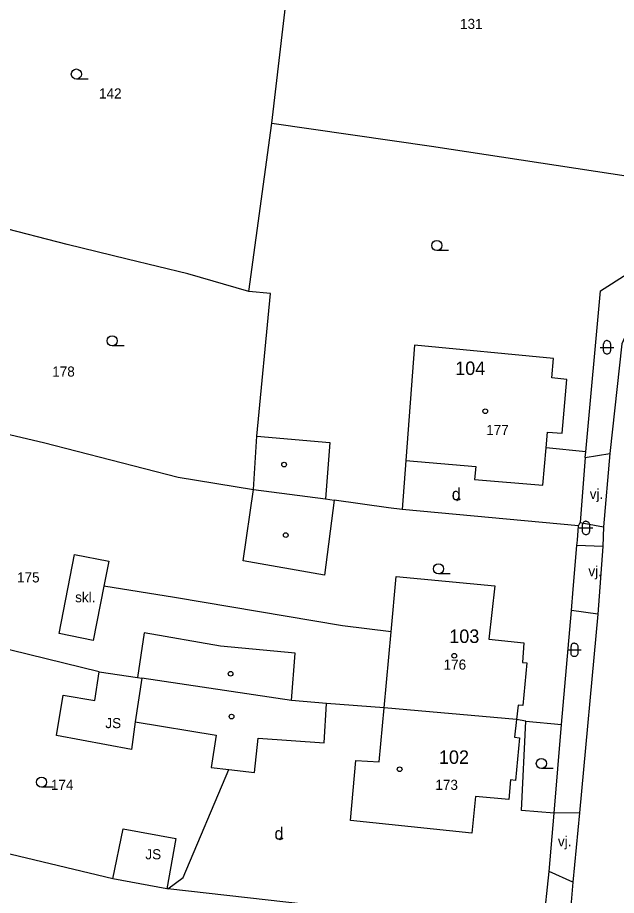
# Model space of a CAD drawing. Extents: x -836739 to -835945, y -1070775 to -1070126.
# Drawn here: x -836577.4 to -836533, y -1070514.1 to -1070449 of the extents above; entities that cross this region are included whole.
import ezdxf

# ---------------------------------------------------------------- set-up
doc = ezdxf.new("R2010")
doc.units = 0
for name, color, linetype in [('BodPole_mer', 7, 'Continuous'), ('Budovy_hranice', 7, 'Continuous'), ('Budovy_kody', 7, 'Continuous'), ('Doprava_hranice', 7, 'Continuous'), ('Doprava_kody', 7, 'Continuous'), ('OstPloch_kody', 7, 'Continuous'), ('RuianAdr_popis', 7, 'Continuous'), ('RuianPar_popis', 7, 'Continuous'), ('Stavby_hr_stav', 7, 'Continuous'), ('Stavby_kody', 7, 'Continuous'), ('Stavby_linie', 7, 'Continuous'), ('Zelen_linie', 7, 'Continuous')]:
    doc.layers.add(name, color=color, linetype=linetype)

msp = doc.modelspace()

# ---------------------------------------------------------------- linework, layer by layer
at = {"layer": 'BodPole_mer'}
for p, q in [((-836558.53, -1070456.83), (-836558.53, -1070456.83)), ((-836546.69, -1070458.52), (-836546.69, -1070458.52)), ((-836573.73, -1070465.81), (-836573.73, -1070465.81)), ((-836569.26, -1070466.91), (-836569.26, -1070466.91)), ((-836564.76, -1070467.99), (-836564.76, -1070467.99)), ((-836534.16, -1070469.25), (-836534.16, -1070469.25)), ((-836560.24, -1070469.31), (-836560.24, -1070469.31)), ((-836558.64, -1070469.45), (-836558.64, -1070469.45)), ((-836547.95, -1070473.29), (-836547.95, -1070473.29)), ((-836537.65, -1070474.28), (-836537.65, -1070474.28)), ((-836537.77, -1070475.71), (-836537.77, -1070475.71)), ((-836536.65, -1070475.84), (-836536.65, -1070475.84)), ((-836559.66, -1070480.04), (-836559.66, -1070480.04)), ((-836538.1, -1070479.75), (-836538.1, -1070479.75)), ((-836537.01, -1070479.82), (-836537.01, -1070479.82)), ((-836575.47, -1070480.52), (-836575.47, -1070480.52)), ((-836554.23, -1070480.51), (-836554.23, -1070480.51)), ((-836538.2, -1070480.91), (-836538.2, -1070480.91)), ((-836535.29, -1070481.63), (-836535.29, -1070481.63)), ((-836535.24, -1070481.2), (-836535.24, -1070481.2)), ((-836533.47, -1070481.32), (-836533.47, -1070481.32)), ((-836548.61, -1070481.84), (-836548.61, -1070481.84)), ((-836543.42, -1070482.28), (-836543.42, -1070482.28)), ((-836565.48, -1070483.09), (-836565.48, -1070483.09)), ((-836543.5, -1070483.26), (-836543.5, -1070483.26)), ((-836559.91, -1070484), (-836559.91, -1070484)), ((-836538.43, -1070483.68), (-836538.43, -1070483.68)), ((-836554.56, -1070484.7), (-836554.56, -1070484.7)), ((-836553.92, -1070484.79), (-836553.92, -1070484.79)), ((-836549.89, -1070485.36), (-836549.89, -1070485.36)), ((-836548.87, -1070485.47), (-836548.87, -1070485.47)), ((-836535.79, -1070486.7), (-836535.79, -1070486.7)), ((-836535.67, -1070486.44), (-836535.67, -1070486.44)), ((-836533.93, -1070486.76), (-836533.93, -1070486.76)), ((-836535.88, -1070487.76), (-836535.88, -1070487.76)), ((-836535.92, -1070488.16), (-836535.92, -1070488.16)), ((-836533.99, -1070488.23), (-836533.99, -1070488.23)), ((-836573.18, -1070488.82), (-836573.18, -1070488.82)), ((-836570.64, -1070489.32), (-836570.64, -1070489.32)), ((-836560.66, -1070489.28), (-836560.66, -1070489.28)), ((-836554.63, -1070490.36), (-836554.63, -1070490.36)), ((-836549.32, -1070490.45), (-836549.32, -1070490.45)), ((-836571, -1070491.16), (-836571, -1070491.16)), ((-836541.99, -1070491.13), (-836541.99, -1070491.13)), ((-836536.18, -1070491.38), (-836536.18, -1070491.38)), ((-836565.76, -1070492.01), (-836565.76, -1070492.01)), ((-836536.32, -1070492.98), (-836536.32, -1070492.98)), ((-836534.36, -1070493.24), (-836534.36, -1070493.24)), ((-836568.01, -1070494.63), (-836568.01, -1070494.63)), ((-836553.29, -1070494.12), (-836553.29, -1070494.12)), ((-836549.7, -1070494.55), (-836549.7, -1070494.55)), ((-836574.31, -1070494.69), (-836574.31, -1070494.69)), ((-836571.79, -1070495.19), (-836571.79, -1070495.19)), ((-836542.44, -1070495.09), (-836542.44, -1070495.09)), ((-836562.36, -1070495.62), (-836562.36, -1070495.62)), ((-836539.84, -1070495.37), (-836539.84, -1070495.37)), ((-836556.81, -1070496.13), (-836556.81, -1070496.13)), ((-836539.96, -1070496.83), (-836539.96, -1070496.83)), ((-836539.62, -1070496.86), (-836539.62, -1070496.86)), ((-836571.36, -1070497.51), (-836571.36, -1070497.51)), ((-836568.5, -1070497.94), (-836568.5, -1070497.94)), ((-836568.18, -1070497.98), (-836568.18, -1070497.98)), ((-836574.02, -1070499.26), (-836574.02, -1070499.26)), ((-836571.68, -1070499.66), (-836571.68, -1070499.66)), ((-836557.09, -1070499.64), (-836557.09, -1070499.64)), ((-836554.49, -1070499.87), (-836554.49, -1070499.87)), ((-836550.21, -1070500.19), (-836550.21, -1070500.19)), ((-836540.27, -1070500), (-836540.27, -1070500)), ((-836539.93, -1070500.03), (-836539.93, -1070500.03)), ((-836540.39, -1070501.06), (-836540.39, -1070501.06)), ((-836568.68, -1070501.24), (-836568.68, -1070501.24)), ((-836539.71, -1070501.19), (-836539.71, -1070501.19)), ((-836537.06, -1070501.42), (-836537.06, -1070501.42)), ((-836574.52, -1070502.25), (-836574.52, -1070502.25)), ((-836562.67, -1070502.22), (-836562.67, -1070502.22)), ((-836559.56, -1070502.45), (-836559.56, -1070502.45)), ((-836540.53, -1070502.37), (-836540.53, -1070502.37)), ((-836540.18, -1070502.42), (-836540.18, -1070502.42)), ((-836554.66, -1070502.78), (-836554.66, -1070502.78)), ((-836568.96, -1070503.28), (-836568.96, -1070503.28)), ((-836552.31, -1070504.09), (-836552.31, -1070504.09)), ((-836550.58, -1070504.19), (-836550.58, -1070504.19)), ((-836563.03, -1070504.61), (-836563.03, -1070504.61)), ((-836561.74, -1070504.76), (-836561.74, -1070504.76)), ((-836559.83, -1070504.98), (-836559.83, -1070504.98)), ((-836540.83, -1070505.53), (-836540.83, -1070505.53)), ((-836540.46, -1070505.58), (-836540.46, -1070505.58)), ((-836543.43, -1070506.77), (-836543.43, -1070506.77)), ((-836540.95, -1070507), (-836540.95, -1070507)), ((-836540.01, -1070507.8), (-836540.01, -1070507.8)), ((-836537.59, -1070508), (-836537.59, -1070508)), ((-836535.73, -1070507.97), (-836535.73, -1070507.97)), ((-836552.71, -1070508.55), (-836552.71, -1070508.55)), ((-836569.58, -1070509.17), (-836569.58, -1070509.17)), ((-836543.71, -1070509.48), (-836543.71, -1070509.48)), ((-836565.67, -1070509.88), (-836565.67, -1070509.88)), ((-836570.33, -1070512.89), (-836570.33, -1070512.89)), ((-836565.13, -1070512.77), (-836565.13, -1070512.77)), ((-836537.96, -1070512.33), (-836537.96, -1070512.33)), ((-836536.22, -1070513.12), (-836536.22, -1070513.12)), ((-836566.34, -1070513.61), (-836566.34, -1070513.61)), ((-836566.25, -1070513.62), (-836566.25, -1070513.62))]:
    msp.add_line(p, q, dxfattribs=at)
at = {"layer": 'Budovy_hranice'}
for points in [[(-836538.43, -1070483.68), (-836538.2, -1070480.91), (-836538.1, -1070479.75), (-836537.01, -1070479.82), (-836536.65, -1070475.84), (-836537.77, -1070475.71), (-836537.65, -1070474.28), (-836547.95, -1070473.29), (-836548.61, -1070481.84), (-836543.42, -1070482.28), (-836543.5, -1070483.26), (-836538.43, -1070483.68)], [(-836559.91, -1070484), (-836559.66, -1070480.04), (-836554.23, -1070480.51), (-836554.56, -1070484.7)], [(-836554.63, -1070490.36), (-836560.66, -1070489.28), (-836559.91, -1070484), (-836554.56, -1070484.7), (-836553.92, -1070484.79), (-836554.63, -1070490.36)], [(-836539.84, -1070495.37), (-836539.96, -1070496.83), (-836539.62, -1070496.86), (-836539.93, -1070500.03), (-836540.27, -1070500), (-836540.39, -1070501.06), (-836550.21, -1070500.19), (-836549.7, -1070494.55), (-836549.32, -1070490.45), (-836541.99, -1070491.13), (-836542.44, -1070495.09), (-836539.84, -1070495.37)], [(-836557.09, -1070499.64), (-836556.81, -1070496.13), (-836562.36, -1070495.62), (-836568.01, -1070494.63), (-836568.5, -1070497.94), (-836568.18, -1070497.98)], [(-836557.09, -1070499.64), (-836568.18, -1070497.98), (-836568.68, -1070501.24), (-836562.67, -1070502.22), (-836563.03, -1070504.61), (-836561.74, -1070504.76), (-836559.83, -1070504.98), (-836559.56, -1070502.45), (-836554.66, -1070502.78), (-836554.49, -1070499.87), (-836557.09, -1070499.64)], [(-836543.43, -1070506.77), (-836543.71, -1070509.48), (-836552.71, -1070508.55), (-836552.31, -1070504.09), (-836550.58, -1070504.19), (-836550.21, -1070500.19)], [(-836540.39, -1070501.06), (-836540.53, -1070502.37), (-836540.18, -1070502.42), (-836540.46, -1070505.58), (-836540.83, -1070505.53), (-836540.95, -1070507), (-836543.43, -1070506.77)]]:
    msp.add_lwpolyline(points, dxfattribs=at)
at = {"layer": 'Budovy_kody'}
for centre in [(-836542.71, -1070478.19), (-836557.63, -1070482.15), (-836557.51, -1070487.38), (-836545.01, -1070496.33), (-836561.6, -1070497.66), (-836561.53, -1070500.84), (-836549.06, -1070504.75)]:
    msp.add_circle(centre, 0.175, dxfattribs=at)
at = {"layer": 'Doprava_hranice'}
for p, q in [((-836535.29, -1070481.63), (-836533.47, -1070481.32)), ((-836535.67, -1070486.44), (-836533.93, -1070486.76)), ((-836533.99, -1070488.23), (-836535.92, -1070488.16)), ((-836534.36, -1070493.24), (-836536.32, -1070492.98)), ((-836535.73, -1070507.97), (-836537.59, -1070508)), ((-836536.22, -1070513.12), (-836537.96, -1070512.33))]:
    msp.add_line(p, q, dxfattribs=at)
msp.add_lwpolyline([(-836531.1, -1070469.82), (-836532.59, -1070473.19), (-836533.47, -1070481.32), (-836533.93, -1070486.76), (-836533.99, -1070488.23), (-836534.36, -1070493.24), (-836535.73, -1070507.97), (-836536.22, -1070513.12), (-836536.82, -1070520.24), (-836537.38, -1070525.89), (-836537.98, -1070532.4), (-836538.73, -1070540.19), (-836539.5, -1070548.26)], dxfattribs=at)
at = {"layer": 'OstPloch_kody'}
for p, q in [((-836572.165, -1070453.55), (-836573.04, -1070453.55)), ((-836545.425, -1070466.27), (-836546.3, -1070466.27)), ((-836569.505, -1070473.34), (-836570.38, -1070473.34)), ((-836534.18, -1070473.45), (-836533.18, -1070473.45)), ((-836533.93, -1070473.7), (-836533.93, -1070473.2)), ((-836533.43, -1070473.2), (-836533.43, -1070473.7)), ((-836535.49, -1070487.1), (-836535.49, -1070486.6)), ((-836534.99, -1070486.6), (-836534.99, -1070487.1)), ((-836535.74, -1070486.85), (-836534.74, -1070486.85)), ((-836545.305, -1070490.26), (-836546.18, -1070490.26)), ((-836536.6, -1070495.89), (-836535.6, -1070495.89)), ((-836536.35, -1070496.14), (-836536.35, -1070495.64)), ((-836535.85, -1070495.64), (-836535.85, -1070496.14)), ((-836537.675, -1070504.7), (-836538.55, -1070504.7)), ((-836574.745, -1070506.08), (-836575.62, -1070506.08))]:
    msp.add_line(p, q, dxfattribs=at)
for points in [[(-836533.68, -1070472.95), (-836533.725, -1070472.954), (-836533.772, -1070472.968), (-836533.817, -1070472.991), (-836533.857, -1070473.023), (-836533.889, -1070473.063), (-836533.912, -1070473.108), (-836533.926, -1070473.155), (-836533.93, -1070473.2)], [(-836533.68, -1070472.95), (-836533.635, -1070472.954), (-836533.588, -1070472.968), (-836533.543, -1070472.991), (-836533.503, -1070473.023), (-836533.471, -1070473.063), (-836533.448, -1070473.108), (-836533.434, -1070473.155), (-836533.43, -1070473.2)], [(-836533.68, -1070473.95), (-836533.725, -1070473.946), (-836533.772, -1070473.932), (-836533.817, -1070473.909), (-836533.857, -1070473.877), (-836533.889, -1070473.837), (-836533.912, -1070473.792), (-836533.926, -1070473.745), (-836533.93, -1070473.7)], [(-836533.43, -1070473.7), (-836533.434, -1070473.745), (-836533.448, -1070473.792), (-836533.471, -1070473.837), (-836533.503, -1070473.877), (-836533.543, -1070473.909), (-836533.588, -1070473.932), (-836533.635, -1070473.946), (-836533.68, -1070473.95)], [(-836544.819, -1070484.79), (-836544.819, -1070484.795), (-836544.818, -1070484.801), (-836544.81, -1070484.805), (-836544.793, -1070484.803), (-836544.763, -1070484.794), (-836544.715, -1070484.773), (-836544.647, -1070484.737), (-836544.554, -1070484.684)], [(-836535.24, -1070486.35), (-836535.285, -1070486.354), (-836535.332, -1070486.368), (-836535.377, -1070486.391), (-836535.417, -1070486.423), (-836535.449, -1070486.463), (-836535.472, -1070486.508), (-836535.486, -1070486.555), (-836535.49, -1070486.6)], [(-836535.24, -1070486.35), (-836535.195, -1070486.354), (-836535.148, -1070486.368), (-836535.103, -1070486.391), (-836535.063, -1070486.423), (-836535.031, -1070486.463), (-836535.008, -1070486.508), (-836534.994, -1070486.555), (-836534.99, -1070486.6)], [(-836535.24, -1070487.35), (-836535.285, -1070487.346), (-836535.332, -1070487.332), (-836535.377, -1070487.309), (-836535.417, -1070487.277), (-836535.449, -1070487.237), (-836535.472, -1070487.192), (-836535.486, -1070487.145), (-836535.49, -1070487.1)], [(-836534.99, -1070487.1), (-836534.994, -1070487.145), (-836535.008, -1070487.192), (-836535.031, -1070487.237), (-836535.063, -1070487.277), (-836535.103, -1070487.309), (-836535.148, -1070487.332), (-836535.195, -1070487.346), (-836535.24, -1070487.35)], [(-836536.1, -1070495.39), (-836536.145, -1070495.394), (-836536.192, -1070495.408), (-836536.237, -1070495.431), (-836536.277, -1070495.463), (-836536.309, -1070495.503), (-836536.332, -1070495.548), (-836536.346, -1070495.595), (-836536.35, -1070495.64)], [(-836536.1, -1070495.39), (-836536.055, -1070495.394), (-836536.008, -1070495.408), (-836535.963, -1070495.431), (-836535.923, -1070495.463), (-836535.891, -1070495.503), (-836535.868, -1070495.548), (-836535.854, -1070495.595), (-836535.85, -1070495.64)], [(-836536.1, -1070496.39), (-836536.145, -1070496.386), (-836536.192, -1070496.372), (-836536.237, -1070496.349), (-836536.277, -1070496.317), (-836536.309, -1070496.277), (-836536.332, -1070496.232), (-836536.346, -1070496.185), (-836536.35, -1070496.14)], [(-836535.85, -1070496.14), (-836535.854, -1070496.185), (-836535.868, -1070496.232), (-836535.891, -1070496.277), (-836535.923, -1070496.317), (-836535.963, -1070496.349), (-836536.008, -1070496.372), (-836536.055, -1070496.386), (-836536.1, -1070496.39)], [(-836557.969, -1070509.96), (-836557.969, -1070509.965), (-836557.968, -1070509.971), (-836557.96, -1070509.975), (-836557.943, -1070509.973), (-836557.913, -1070509.964), (-836557.865, -1070509.943), (-836557.797, -1070509.907), (-836557.704, -1070509.854)]]:
    msp.add_lwpolyline(points, dxfattribs=at)
for centre in [(-836573.04, -1070453.175), (-836546.3, -1070465.895), (-836570.38, -1070472.965), (-836546.18, -1070489.885), (-836538.55, -1070504.325), (-836575.62, -1070505.705)]:
    msp.add_ellipse(centre, major_axis=(0.375, 0), ratio=0.999999, dxfattribs=at)
at = {"layer": 'RuianAdr_popis'}
for p, q in [((-836544.94, -1070475.5), (-836544.94, -1070475.5)), ((-836545.38, -1070495.38), (-836545.38, -1070495.38)), ((-836546.15, -1070504.35), (-836546.15, -1070504.35))]:
    msp.add_line(p, q, dxfattribs=at)
at = {"layer": 'RuianPar_popis'}
for p, q in [((-836544.58, -1070449.83), (-836544.58, -1070449.83)), ((-836571.36, -1070454.99), (-836571.36, -1070454.99)), ((-836574.83, -1070475.62), (-836574.83, -1070475.62)), ((-836542.64, -1070479.95), (-836542.64, -1070479.95)), ((-836545.8, -1070497.36), (-836545.8, -1070497.36)), ((-836574.93, -1070506.28), (-836574.93, -1070506.28)), ((-836546.41, -1070506.28), (-836546.41, -1070506.28))]:
    msp.add_line(p, q, dxfattribs=at)
at = {"layer": 'Stavby_hr_stav'}
for points in [[(-836570.64, -1070489.32), (-836571, -1070491.16), (-836571.79, -1070495.19), (-836574.31, -1070494.69), (-836573.18, -1070488.82), (-836570.64, -1070489.32)], [(-836568.68, -1070501.24), (-836568.96, -1070503.28), (-836574.52, -1070502.25), (-836574.02, -1070499.26), (-836571.68, -1070499.66), (-836571.36, -1070497.51), (-836568.5, -1070497.94)], [(-836570.33, -1070512.89), (-836569.58, -1070509.17), (-836565.67, -1070509.88), (-836566.34, -1070513.61), (-836570.33, -1070512.89)]]:
    msp.add_lwpolyline(points, dxfattribs=at)
at = {"layer": 'Stavby_linie'}
for p, q in [((-836573.73, -1070465.81), (-836587.35, -1070462.31)), ((-836535.24, -1070481.2), (-836538.2, -1070480.91)), ((-836535.29, -1070481.63), (-836535.67, -1070486.44)), ((-836548.61, -1070481.84), (-836548.87, -1070485.47)), ((-836565.48, -1070483.09), (-836559.91, -1070484)), ((-836550.21, -1070500.19), (-836554.49, -1070499.87)), ((-836539.71, -1070501.19), (-836537.06, -1070501.42)), ((-836537.59, -1070508), (-836537.06, -1070501.42)), ((-836537.96, -1070512.33), (-836537.59, -1070508))]:
    msp.add_line(p, q, dxfattribs=at)
for points in [[(-836560.24, -1070469.31), (-836558.53, -1070456.83), (-836556.87, -1070442.42), (-836554.53, -1070432.32), (-836553.8, -1070429), (-836550.67, -1070422.72)], [(-836535.29, -1070481.63), (-836535.24, -1070481.2), (-836534.16, -1070469.25), (-836530.49, -1070466.92), (-836529.34, -1070461.16), (-836525.7, -1070445.11)], [(-836558.53, -1070456.83), (-836546.69, -1070458.52), (-836529.34, -1070461.16)], [(-836560.24, -1070469.31), (-836564.76, -1070467.99), (-836569.26, -1070466.91), (-836573.73, -1070465.81)], [(-836559.66, -1070480.04), (-836558.64, -1070469.45), (-836560.24, -1070469.31)], [(-836589.2, -1070477.29), (-836575.47, -1070480.52), (-836565.48, -1070483.09)], [(-836535.79, -1070486.7), (-836548.87, -1070485.47), (-836549.89, -1070485.36), (-836553.92, -1070484.79)], [(-836535.88, -1070487.76), (-836535.79, -1070486.7), (-836535.67, -1070486.44)], [(-836536.18, -1070491.38), (-836535.92, -1070488.16), (-836535.88, -1070487.76)], [(-836549.7, -1070494.55), (-836553.29, -1070494.12), (-836565.76, -1070492.01), (-836571, -1070491.16)], [(-836537.06, -1070501.42), (-836536.32, -1070492.98), (-836536.18, -1070491.38)], [(-836571.36, -1070497.51), (-836588.31, -1070493.37), (-836591.23, -1070492.73)], [(-836537.59, -1070508), (-836540.01, -1070507.8), (-836539.71, -1070501.19), (-836540.39, -1070501.06)], [(-836570.33, -1070512.89), (-836581.41, -1070510.24), (-836593.12, -1070507.61)], [(-836538.83, -1070521.16), (-836538.74, -1070520.16), (-836538.4, -1070516.3), (-836537.96, -1070512.33)], [(-836538.4, -1070516.3), (-836547.13, -1070515.54), (-836555.98, -1070514.79), (-836566.25, -1070513.62), (-836566.34, -1070513.61)]]:
    msp.add_lwpolyline(points, dxfattribs=at)
at = {"layer": 'Zelen_linie'}
msp.add_lwpolyline([(-836566.25, -1070513.62), (-836565.13, -1070512.77), (-836561.74, -1070504.76)], dxfattribs=at)

# ---------------------------------------------------------------- texts
at = {"layer": 'Doprava_kody'}
for p in [(-836534.96, -1070484.7), (-836535.06, -1070490.43), (-836537.32, -1070510.47)]:
    msp.add_text('vj.', height=0.75, dxfattribs=at).set_placement(p)
at = {"layer": 'OstPloch_kody'}
for p in [(-836545.195, -1070484.79), (-836558.345, -1070509.96)]:
    msp.add_text('d', height=0.9, dxfattribs=at).set_placement(p)
at = {"layer": 'RuianAdr_popis'}
for s, p in [('104', (-836544.94, -1070475.5)), ('103', (-836545.38, -1070495.38)), ('102', (-836546.15, -1070504.35))]:
    msp.add_text(s, height=1, dxfattribs=at).set_placement(p)
at = {"layer": 'RuianPar_popis'}
for s, p in [('131', (-836544.58, -1070449.83)), ('142', (-836571.36, -1070454.99)), ('178', (-836574.83, -1070475.62)), ('177', (-836542.64, -1070479.95)), ('175', (-836577.44, -1070490.89)), ('176', (-836545.8, -1070497.36)), ('174', (-836574.93, -1070506.28)), ('173', (-836546.41, -1070506.28))]:
    msp.add_text(s, height=0.75, dxfattribs=at).set_placement(p)
at = {"layer": 'Stavby_kody'}
for s, p in [('skl.', (-836573.13, -1070492.36)), ('JS', (-836570.89, -1070501.7)), ('JS', (-836567.92, -1070511.43))]:
    msp.add_text(s, height=0.75, dxfattribs=at).set_placement(p)

doc.saveas('drawing.dxf')
